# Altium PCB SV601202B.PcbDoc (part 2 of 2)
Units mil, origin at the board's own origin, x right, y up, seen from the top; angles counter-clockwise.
Board outline 3713 x 4037 mil, 6 copper layers (Top Layer, Signal Layer 1, Signal Layer 2, Signal Layer 3, Signal Layer 4, Bottom Layer), stack 60.36 mil thick; 230 components, 115 nets, 621 pads, 197 vias.
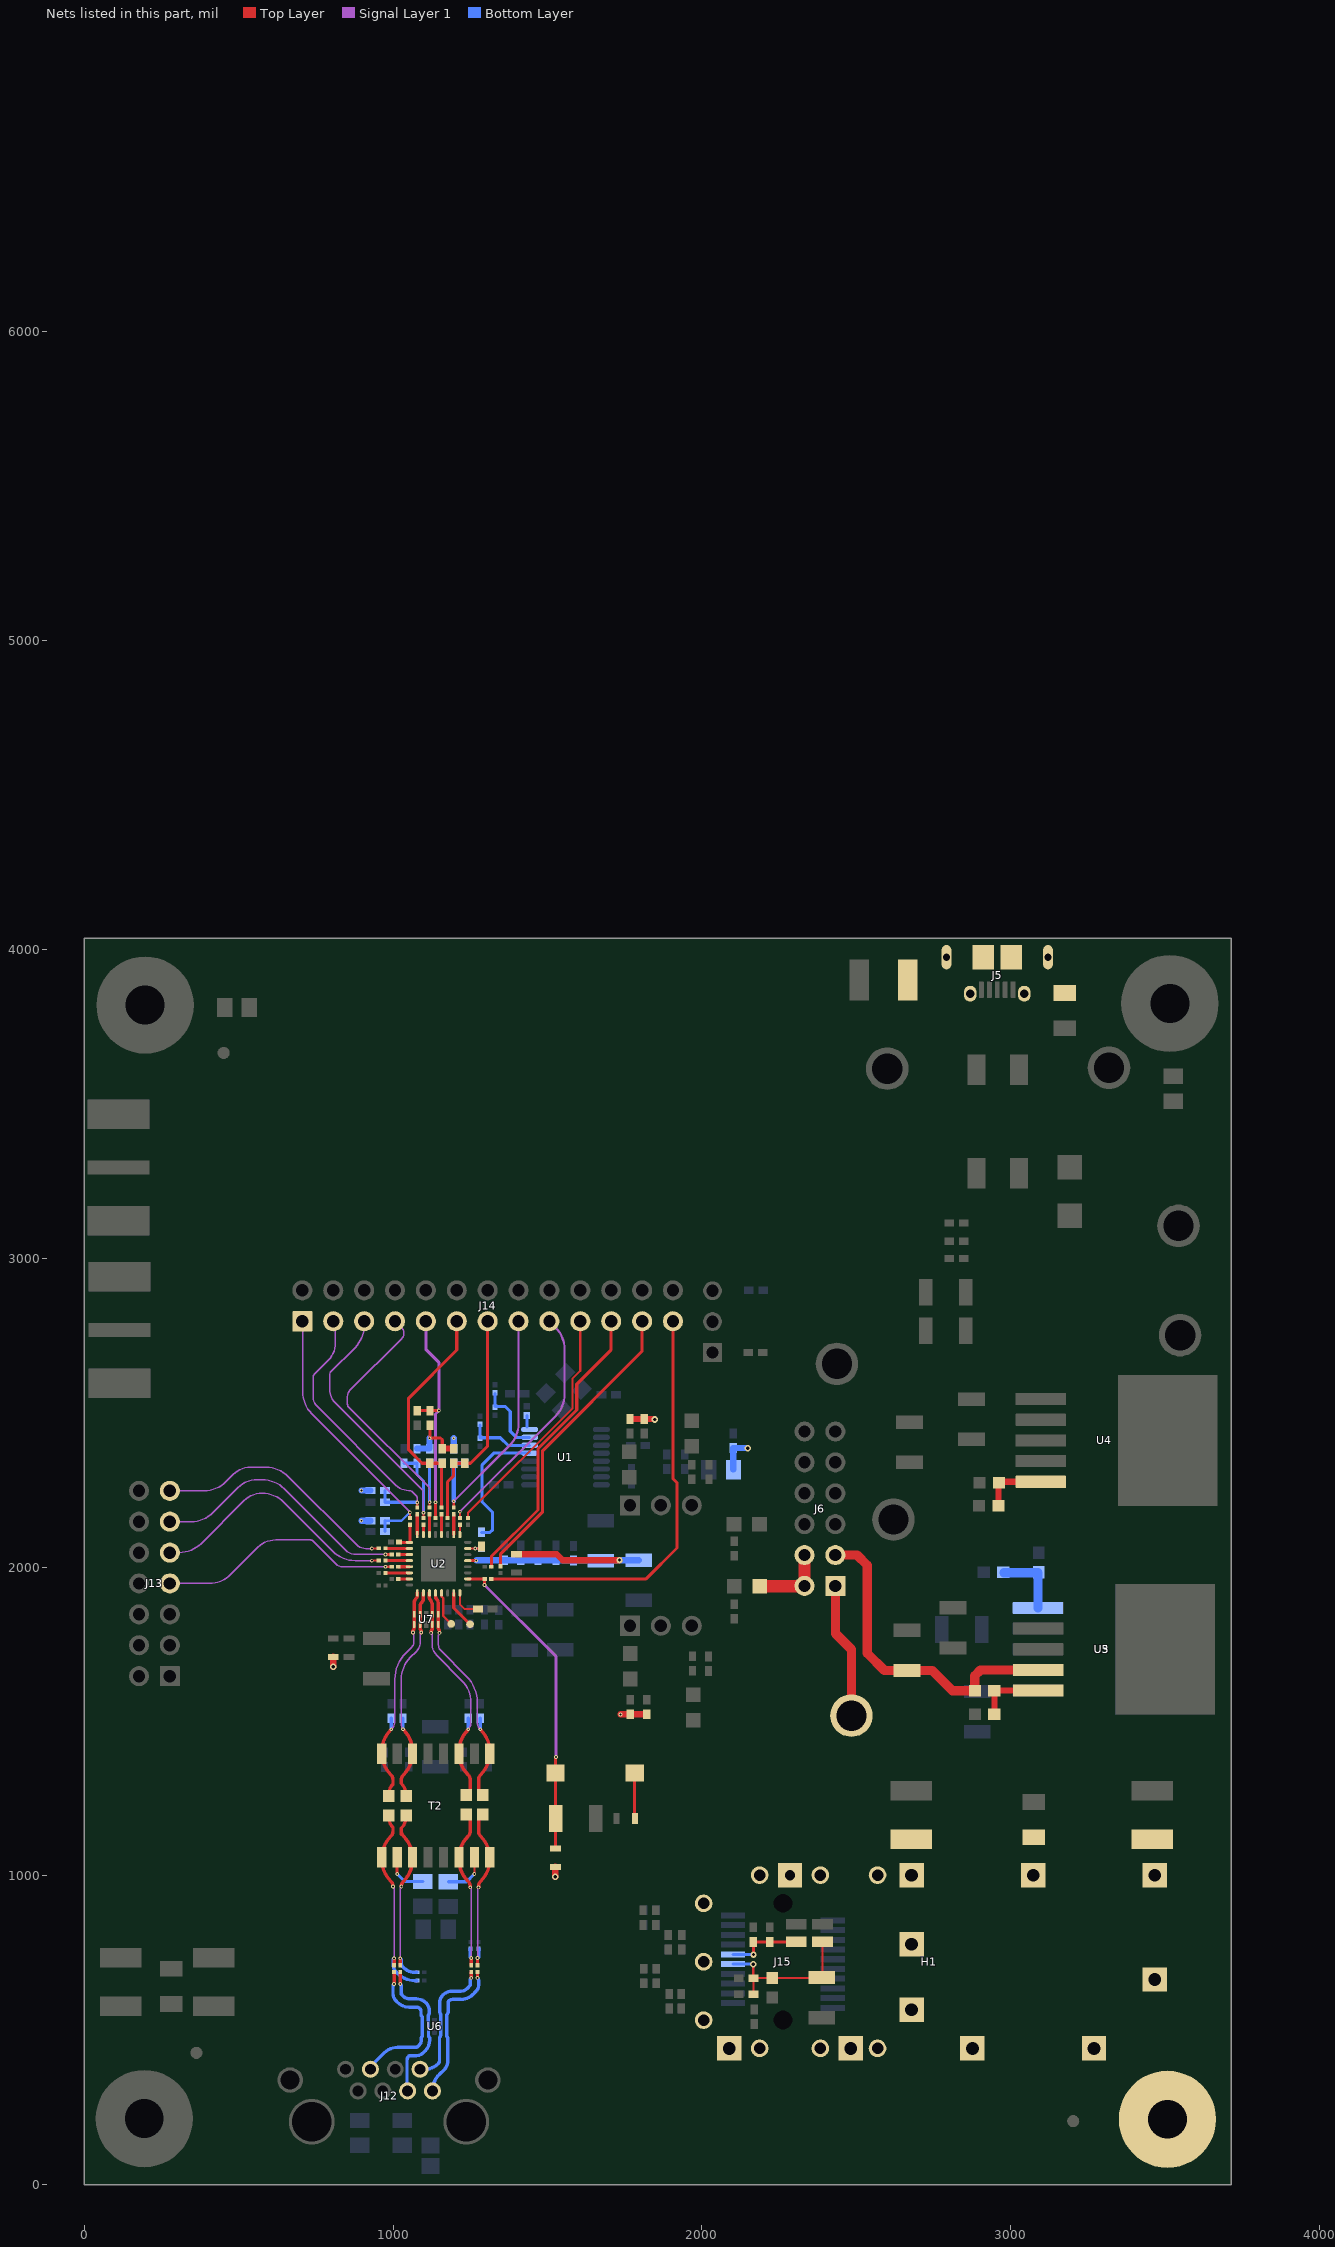
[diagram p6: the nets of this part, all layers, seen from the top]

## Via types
v1: diameter 22, hole 11, Top Layer to Bottom Layer, 107 vias
v2: diameter 12, hole 6, Top Layer to Bottom Layer, 74 vias
v3: diameter 20, hole 10, Top Layer to Bottom Layer, 10 vias
v4: diameter 19.68, hole 7.87, Top Layer to Bottom Layer, 5 vias
v5: diameter 25, hole 12, Top Layer to Bottom Layer, 1 vias

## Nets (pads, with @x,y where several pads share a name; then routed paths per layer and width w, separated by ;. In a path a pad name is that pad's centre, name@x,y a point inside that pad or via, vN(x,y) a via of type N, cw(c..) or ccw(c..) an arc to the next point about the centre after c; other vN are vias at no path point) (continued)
NetJ13_7: J13.7 R50.1 | length 802.7
  Top Layer w7: v2(975,2001) R50.1@994.98,2001
  Signal Layer 1 w4.5: J13.7@277,1947 403.58,1947 ccw(c403.58,2047) 474.29,1976.29 562,2064 cw(c619.94,2006.06) 619.94,2088 730,2088 cw(c730,2071.1) 741.94,2083.06 816,2009 ccw(c835.31,2028.31) 835.31,2001 v2(975,2001)
NetJ13_9: J13.9 R51.1 | length 798.7
  Top Layer w7: v2(931,2021) R51.1@952.98,2021
  Signal Layer 1 w4.5: J13.9@307.58,2047 ccw(c307.58,2147) 378.29,2076.29 516.55,2214.55 cw(c575.58,2155.52) 575.58,2239 cw(c575.58,2139) 646.29,2209.71 805.71,2050.29 ccw(c876.42,2121) 876.42,2021 v2(931,2021)
NetJ13_11: J13.11 R52.1 | length 860.1
  Top Layer w10: v2(975,2041) R52.1@994.98,2041
  Signal Layer 1 w4.5: J13.11@277,2147 345.58,2147 ccw(c345.58,2247) 416.29,2176.29 497,2257 cw(c559.77,2194.23) 559.77,2283 576.58,2283 cw(c576.58,2183) 647.29,2253.71 846,2055 ccw(c879.8,2088.8) 879.8,2041 v2(975,2041)
NetJ13_13: J13.13 R54.1 | length 802.5
  Top Layer w7: v2(931,2060) R54.1@952.98,2060
  Signal Layer 1 w4.5: J13.13@277,2247 387.58,2247 ccw(c387.58,2347) 458.29,2276.29 482,2300 cw(c537.53,2244.47) 537.53,2323 588.58,2323 cw(c588.58,2223) 659.29,2293.71 879.69,2073.31 ccw(c911.83,2105.46) 911.83,2060 v2(931,2060)
NetJ14_1: J14.1 R56.1 R80.1 R82.2 | length 902.6
  Top Layer w7: R56.1@1055,2159.02 v2@1055,2176
  Signal Layer 1 w4.5: J14.1@706,2767 cw(c703.59,2764.59) J14.1@707,2764.59 ; J14.1@707,2796 J14.1@707,2764.59 ; v2@1054,2179 736.29,2496.71 cw(c807,2567.42) 707,2567.42 J14.1@707,2764.59
  Bottom Layer w7: R80.1@973.62,2150 1027,2150 v2(1054,2177)
  Bottom Layer w10: R82.2@973.62,2115 R80.1@973.62,2150
NetJ14_3: J14.3 R57.1 R77.1 R78.2 | length 924
  Top Layer w7: R57.1@1078,2193.02 v2(1078,2209)
  Signal Layer 1 w4.5: J14.3@806,2796 cw(c789.1,2779.1) 813,2779.1 813,2726 cw(c733.33,2726) 789.67,2669.67 746,2626 ccw(c758.07,2613.93) 741,2613.93 741,2551 ccw(c784.46,2551) 753.73,2520.27 1008.32,2265.68 ccw(c1051,2308.36) 1051,2248 cw(c1051,2233.51) 1061.24,2243.76 1074.46,2230.54 cw(c1065.93,2222) 1078,2222 v2(1078,2209)
  Bottom Layer w10: R77.1@973.62,2248 R78.2@973.62,2210 v2@1077,2210
NetJ14_5: J14.5 R58.1 R75.1 R76.2 | length 1012
  Top Layer w7: R58.1@1098,2159.02 v2(1098,2176)
  Signal Layer 1 w4.5: J14.5@906,2796 906,2781.42 cw(c806,2781.42) 876.71,2710.71 798,2632 ccw(c807.66,2622.34) 794,2622.34 794,2578 ccw(c861.6,2578) 813.8,2530.2 1094,2250 cw(c1084.34,2240.34) 1098,2240.34 v2(1098,2176)
  Bottom Layer w10: R76.2@1035,2336.38 R75.1@1077,2336.38 1077,2300 1098,2279 v2(1098,2176)
NetJ14_7: J14.7 R59.1 R71.1 R72.2 | length 963.8
  Top Layer w7: R59.1@1118,2193.02 v2(1118,2210)
  Signal Layer 1 w4.5: J14.7@1006,2796 1028.64,2773.36 cw(c1013.27,2758) 1035,2758 cw(c1008.44,2758) 1027.22,2739.22 860,2572 ccw(c879.31,2552.69) 852,2552.69 852,2528 ccw(c866.49,2528) 856.23,2517.77 1113,2261 cw(c1100.93,2248.93) 1118,2248.93 v2(1118,2210)
  Bottom Layer w10: v2(1118,2210) R71.1@1118,2336.38 R72.2@1159,2336.38
NetJ14_9: J14.9 R61.1 R84.1 R88.2 | length 728.6
  Top Layer w10: R88.2@1078,2506.62 v2@1147.62,2506.62 ; R61.1@1137,2159.02 v2(1137,2210)
  Signal Layer 1 w10: J14.9@1106,2796 1106,2705 1148,2663 v2(1148,2507) 1137,2496 v2(1137,2210)
NetJ14_11: J14.11 R60.1 R62.1 R66.2 | length 746.3
  Top Layer w10: R62.1@1156,2193.02 1156,2333.38 1153,2336.38 R66.2@1118,2336.38 1093.62,2336.38 1050,2380 1050,2547 1206,2703 J14.11@1206,2796
NetJ14_13: J14.13 R53.1 R55.2 R63.1 | length 722.7
  Top Layer w10: R63.1@1176,2159.02 1176,2276 1196,2296 R53.1@1196,2336.38 1250.38,2336.38 1306,2392 J14.13@1306,2796
NetJ14_15: J14.15 R45.1 R48.2 R64.1 | length 845
  Top Layer w7: R64.1@1196,2193.02 v2(1196,2213)
  Signal Layer 1 w7: v2(1196,2213) 1376.71,2393.71 ccw(c1306,2464.42) 1406,2464.42 J14.15@1406,2796
  Bottom Layer w15: v2(1196,2213) R45.1@1196,2336.38 R48.2@1232,2336.38
NetJ14_17: J14.17 R65.1 | length 789.1
  Top Layer w7: R65.1@1216,2159.02 v2(1216,2179)
  Signal Layer 1 w7: v2(1216,2179) 1525.71,2488.71 ccw(c1455,2559.42) 1555,2559.42 1555,2705.58 ccw(c1455,2705.58) 1525.71,2776.29 J14.17@1506,2796
NetJ14_19: J14.19 R67.1 | length 787.8
  Top Layer w7: R67.1@1242,2159.02 1242,2175 1581,2514 1581,2611 1606,2636 J14.19@1606,2796
NetJ14_21: J14.21 R68.1 | length 955.7
  Top Layer w10: R68.1@1318.02,2001 1318.02,2034.02 1469,2185 1469,2382.91 1594.5,2508.41 1594.5,2592.5 1706,2704 J14.21@1706,2796
NetJ14_23: J14.23 R69.1 | length 982.7
  Top Layer w10: R69.1@1348,2003.02 1348,2042.79 1484,2178.79 1484,2376.69 1806,2698.69 J14.23@1806,2796
NetJ14_25: J14.25 R70.1 | length 1381.8
  Top Layer w10: R70.1@1318.02,1962 1819,1962 1919,2062 1919,2273 1906,2286 J14.25@1906,2796
NetR3_1: R3.1 U1.13 | length 433.1
  Bottom Layer w10: R3.1@1286,2112.62 1313.62,2112.62 1322,2121 1322,2177 1288,2211 1288,2331 1325.8,2368.8 U1.13@1441.86,2368.8
NetR10_2: R10.2 S1.2 | length 146.4
  Top Layer w10: R10.2@1781.95,1186.57 S1.2@1781.95,1333
NetR14_1: R14.1 R15.2 U3.5 | length 223.5
  Bottom Layer w30: R14.1@2978.06,1981.44 3087.94,1981.44 U3.5@3087.94,1867.86
NetR19_1: R19.1 R21.2 U4.5 | length 215.6
  Top Layer w7: U4.5@3093.8,2273 U4.5@3096.94,2276.14
  Top Layer w20: R21.2@2960.5,2199 2960.5,2272 R19.1@2961.5,2273 2964.64,2276.14 U4.5@3096.94,2276.14
NetR26_1: R26.1 R27.2 U5.5 | length 219.8
  Top Layer w10: U5.5@3087.8,1600 U5.5@3087.94,1600.14
  Top Layer w20: R27.2@2947.64,1520.86 2947.64,1600.14 U5.5@3087.94,1600.14
NetR34_2: R34.2 T2.10 | length 142.5
  Top Layer w10: v2(1013,1006) T2.10@1013,1055.56
  Bottom Layer w10: v2(1013,1006) 1037,982 R34.2@1096,982
NetR35_2: R35.2 T2.15 | length 143.9
  Top Layer w7: v2(1263,1006) T2.15@1263,1055.56
  Bottom Layer w10: R35.2@1179,981 1238,981 v2(1263,1006)
NetR92_2: R92.2 U1.16 | length 36.6
  Bottom Layer w10: U1.16@1433,2454.43 R92.2@1433,2491.04
NetR93_1: R93.1 R95.2 U1.15 | length 232.8
  Bottom Layer w10: R95.2@1330,2562.04 1330,2519.96 1363.04,2519.96 1379,2504 1379,2440 1399.02,2419.98 U1.15@1441.86,2419.98
NetR94_1: R94.1 R96.2 U1.14 | length 212.1
  Bottom Layer w10: R94.1@1281,2460.04 1281,2418.96 1347.04,2418.96 1371.61,2394.39 U1.14@1441.86,2394.39
NetTP1_1: TP1.1 U2.13 | length 113.4
  Top Layer w7.5: U2.13@1156.84,1916.51 1156.84,1905.16 1162,1900 1162,1842 TP1.1@1188,1816
NetTP2_1: TP2.1 U2.15 | length 123.4
  Top Layer w10: U2.15@1196.21,1916.51 1196.21,1867.79 TP2.1@1249,1815
PWR_CHASSIS: C28.2 J5.6 J5.7 J5.8 J5.9 J5.10 J5.11 R11.1
RBIAS: Rs1.2 U2.16 | length 101.6
  Top Layer w7: U2.16@1215.9,1916.51 1215.9,1880.1 1232,1864 Rs1.2@1274.38,1864
RESET_N: C27.1 R8.1 R70.2 S1.1 U2.18 | length 1021.4
  Top Layer w10: U2.18@1241.49,1961.79 R70.2@1295.76,1961.79 ; v2(1296,1942) R70.2@1295.98,1962 ; R8.1@1526.04,1089.57 C27.1@1526.04,1186 S1.1@1526.05,1333 v2@1526.05,1384.05
  Signal Layer 1 w10: v2(1296,1942) 1527,1711 v2(1527,1385)
RX_CLK: R65.2 U2.25 | length 31.4
  Top Layer w7: U2.25@1215.9,2105.49 R65.2@1215.9,2136.87
RX_D0: R59.2 U2.30 | length 65.6
  Top Layer w10: U2.30@1117.47,2105.49 1117.47,2169.7 cw(c1119.27,2169.7) R59.2@1118,2170.98
RX_D1: R58.2 U2.31 | length 31.3
  Top Layer w10: U2.31@1097.79,2105.49 R58.2@1097.79,2136.76
RX_D2: R57.2 U2.32 | length 65.4
  Top Layer w10: U2.32@1078.1,2105.49 R57.2@1078.1,2170.87
RX_D3: R7.2 R56.2 U2.1 | length 89.9
  Top Layer w10: R7.2@1020.09,2079.9 U2.1@1052.51,2079.9 ccw(c1048.92,2083.49) 1054,2083.49 R56.2@1054,2136.98
RX_DV: R64.2 U2.26 | length 65.3
  Top Layer w10: U2.26@1196.21,2105.49 R64.2@1196.21,2170.76
RX_ER: R62.2 U2.28 | length 65.7
  Top Layer w10: R62.2@1156,2170.98 cw(c1153.97,2168.94) 1156.84,2168.94 U2.28@1156.84,2105.49
RXD_CABLE_N: J12.6 R28.2 U6.5 U6.6 | length 496.4
  Top Layer w11: v2(1003,650) R28.2@1003,688.98
  Bottom Layer w11: J12.6@926.37,373.99 cw(c946.6,373.99) 932.29,388.29 971,427 cw(c1014.46,383.54) 1014.46,445 1074.17,445 ccw(c1074.17,451.83) 1078.99,446.99 1085.3,453.3 ccw(c1071.59,467) 1090.97,467 1090.97,476.28 ccw(c1082.14,485.11) 1094.63,485.11 1094.63,496.27 1094.63,529.73 1094.63,539.24 ccw(c1082.24,539.24) 1091,548 cw(c1093.41,550.41) 1090,550.41 1090,562.76 ccw(c1079.76,562.76) 1087,570 ccw(c1074.93,557.93) 1074.93,575 1052.31,575 cw(c1052.31,629.31) 1013.91,590.91 1009.18,595.64 cw(c1032.54,619) 999.5,619 999.5,641.55 cw(c1011.45,641.55) v2(1003,650)
RXD_CABLE_P: J12.3 R29.2 U6.4 U6.7 | length 498.9
  Top Layer w11: v2(1023,650) R29.2@1023,688.98
  Bottom Layer w11: v2(1023,650) cw(c1014.55,641.55) 1026.5,641.55 1026.5,619 ccw(c1032.54,619) 1028.27,614.73 1033,610 ccw(c1052.31,629.31) 1052.31,602 1074.93,602 cw(c1074.93,557.93) 1106.09,589.09 cw(c1079.76,562.76) 1117,562.76 1117,557 cw(c1104.93,557) 1113.46,548.46 1113.46,531.79 ccw(c1116.37,531.79) 1114.32,529.73 1114.32,496.27 1114.32,485.11 ccw(c1126.8,485.11) 1117.97,476.28 1117.97,467 cw(c1071.59,467) 1104.39,434.2 1098.09,427.91 cw(c1074.17,451.83) 1074.17,418 1054,418 ccw(c1054,413.17) 1050.59,416.59 ccw(c1064.69,402.48) 1044.74,402.48 1044.74,308.98 ccw(c1051.91,308.98) J12.3@1046.84,303.91
RXD_MAG_N: C47.1 R28.1 R36.1 T2.9 | length 630.6
  Top Layer w11: C47.1@986,1195.5 986,1189.41 ccw(c1032.09,1189.41) 999.5,1156.82 999.5,1145.36 cw(c974.88,1145.36) 992.29,1127.95 ccw(c1063,1057.24) 963,1057.24 963,1055.56 963,1053.88 ccw(c1063,1053.88) 992.29,983.17 cw(c974.88,965.76) v2(999.5,965.76) ; R28.1@1003,711.02 v2(1003,733)
  Signal Layer 1 w4.5: v2(999.5,965.76) cw(c991.65,957.92) 1002.75,957.92 v2@1002.75,733
  Bottom Layer w11: v2(1003,733) ccw(c1011.45,724.55) 999.5,724.55 999.5,714 ccw(c1034.95,714) 1009.88,688.93 1014.91,683.91 ccw(c1070.21,739.21) 1070.21,661 R36.1@1076,661
RXD_MAG_P: C48.1 R29.1 R41.1 T2.11 | length 599.9
  Top Layer w11: R29.1@1023,711.02 v2(1023,733) ; v2(1026.5,965.76) cw(c1051.12,965.76) 1033.71,983.17 ccw(c963,1053.88) 1063,1053.88 1063,1055.56 1063,1057.24 ccw(c963,1057.24) 1033.71,1127.95 cw(c1051.12,1145.36) 1026.5,1145.36 ; 1026.5,1134.17 1026.5,1145.36 ; C48.1@1042,1195.5 1042,1192.24 cw(c989.08,1192.24) 1026.5,1154.82 1026.5,1145.36
  Signal Layer 1 w4.5: v2@1023.25,733 1023.25,957.92 cw(c1034.35,957.92) v2(1026.5,965.76)
  Bottom Layer w11: v2(1023,733) cw(c1014.55,724.55) 1026.5,724.55 1026.5,714 ccw(c1034.95,714) 1028.97,708.03 1034,703 ccw(c1070.21,739.21) 1070.21,688 R41.1@1076,688
RXD_N: C47.2 R39.1 T2.8 U2.9 U7.1 U7.10 | length 739.4
  Top Layer w11: C47.2@986,1258.5 986,1264.59 cw(c1032.09,1264.59) 999.5,1297.18 999.5,1310.65 ccw(c974.88,1310.65) 992.29,1328.05 cw(c1063,1398.76) 963,1398.76 963,1400.44 963,1402.12 cw(c1063,1402.12) v2@992.29,1472.83 ; v2(1063.97,1788) 1063.97,1794.28 ccw(c1055.14,1803.11) 1067.63,1803.11 1067.63,1814.27 1067.63,1847.73 1067.63,1881.21 cw(c1092.79,1881.21) 1075,1899 ccw(c1067.51,1906.49) 1078.1,1906.49 U2.9@1078.1,1916.51
  Signal Layer 1 w4.5: v2(994,1475) ccw(c966.24,1502.76) 1005.5,1502.76 1005.5,1636.59 cw(c1126,1636.59) 1040.79,1721.79 1059.6,1740.6 ccw(c1041.2,1759) 1067.22,1759 1067.22,1780.15 ccw(c1056.13,1780.15) v2(1063.97,1788)
  Bottom Layer w11: v2(994,1475) R39.1@994,1510.38
RXD_P: C48.2 R40.1 T2.6 U2.10 U7.2 U7.9 | length 738.5
  Top Layer w11: v2@1033.71,1472.83 cw(c963,1402.12) 1063,1402.12 1063,1400.44 1063,1398.76 cw(c963,1398.76) 1033.71,1328.05 ccw(c1051.12,1310.65) 1026.5,1310.65 1026.5,1299.18 cw(c989.08,1261.76) 1042,1261.76 C48.2@1042,1258.5 ; v2(1090.97,1788) 1090.97,1794.28 cw(c1099.8,1803.11) 1087.31,1803.11 1087.31,1814.27 1087.31,1847.73 1087.31,1873.69 cw(c1103.31,1873.69) 1092,1885 ccw(c1078.03,1898.97) 1097.79,1898.97 U2.10@1097.79,1916.51
  Signal Layer 1 w4.5: v2(1032,1475) cw(c1046.49,1489.49) 1026,1489.49 1026,1636.59 cw(c1126,1636.59) 1055.29,1707.3 1074.1,1726.11 ccw(c1041.2,1759) 1087.72,1759 1087.72,1780.15 cw(c1098.82,1780.15) v2(1090.97,1788)
  Bottom Layer w11: v2(1032,1475) R40.1@1032,1510.38
SFP_EARTH: C66.2 C67.2 H1.1 H1.2 H1.3 H1.4 H1.5 H1.6 H1.7 H1.8 H1.9 H1.10 H1.11 H1.12 H1.MH1 H1.MH2 H1.MH3 H1.MH4 H1.MH5 H1.MH6 H1.MH7 H1.MH8 M2.1 R83.1
TX_CLK: R54.2 U2.2 | length 77.3
  Top Layer w10: R54.2@975.24,2060.21 U2.2@1052.51,2060.21
TX_D0: R51.2 U2.4 | length 77.3
  Top Layer w10: R51.2@975.18,2020.84 U2.4@1052.51,2020.84
TX_D1: R50.2 U2.5 | length 35.3
  Top Layer w10: R50.2@1017.18,2001.16 U2.5@1052.51,2001.16
TX_D2: R49.2 U2.6 | length 77.6
  Top Layer w10: R49.2@975.02,1982 ccw(c976.3,1983.27) 976.3,1981.47 U2.6@1052.51,1981.47
TX_D3: R47.2 U2.7 | length 35.3
  Top Layer w10: R47.2@1017.24,1961.79 U2.7@1052.51,1961.79
TX_EN: R52.2 U2.3 | length 35.6
  Top Layer w10: R52.2@1017.02,2041 ccw(c1018.16,2042.14) 1018.16,2040.53 U2.3@1052.51,2040.53
TXD_CABLE_N: J12.2 R30.2 U6.2 U6.9 | length 434.1
  Top Layer w11: v2(1253,670) R30.2@1253,688.98
  Bottom Layer w11: J12.2@1087,373.99 1102.53,373.99 ccw(c1102.53,435.47) 1146,392 ccw(c1136.28,401.72) 1150.03,401.72 1150.03,476.28 ccw(c1141.2,485.11) 1153.69,485.11 1153.69,496.27 U6.9@1153.69,529.73 ; U6.9@1153.91,529.96 1153.91,552.91 cw(c1160.93,559.93) 1151,559.93 1151,590.17 cw(c1184.83,590.17) 1160.91,614.09 cw(c1192.07,582.93) 1192.07,627 1219.69,627 ccw(c1219.69,654.31) 1238.99,634.99 1249.5,645.5 1249.5,661.55 cw(c1261.45,661.55) v2(1253,670)
TXD_CABLE_P: J12.1 R31.2 U6.1 U6.10 | length 473.6
  Top Layer w11: v2(1273,670) R31.2@1273,688.98
  Bottom Layer w11: J12.1@1127.16,303.91 cw(c1202.14,303.91) 1149.11,356.93 1165.09,372.91 ccw(c1136.28,401.72) 1177.03,401.72 1177.03,476.28 cw(c1185.86,485.11) 1173.37,485.11 1173.37,496.27 1173.37,529.73 1173.37,547.65 cw(c1182.35,547.65) 1176,554 ccw(c1171.17,558.83) 1178,558.83 1178,590.17 cw(c1184.83,590.17) 1180,595 cw(c1192.07,582.93) 1192.07,600 1219.69,600 ccw(c1219.69,654.31) 1258.09,615.91 1268.24,626.05 ccw(c1248.29,646) 1276.5,646 1276.5,661.55 ccw(c1264.55,661.55) v2(1273,670)
TXD_MAG_N: C49.1 R30.1 R42.1 T2.14 | length 543.6
  Top Layer w11: C49.1@1237,1198.5 1242.5,1193 cw(c1224.39,1174.9) 1250,1174.9 1250,1148 ; v2(1249.5,963) 1249.5,965.76 ccw(c1224.88,965.76) 1242.29,983.17 cw(c1313,1053.88) 1213,1053.88 1213,1055.56 1213,1057.24 cw(c1313,1057.24) 1242.29,1127.95 ccw(c1224.88,1145.36) 1249.5,1145.36 1249.5,1148 ; v2(1252.75,734) 1253,733.75 R30.1@1253,711.02
  Signal Layer 1 w4.5: v2(1249.5,963) cw(c1241.65,955.15) 1252.75,955.15 v2(1252.75,734)
  Bottom Layer w11: R42.1@1249.5,764 1249.5,737.25 v2(1252.75,734)
TXD_MAG_P: C50.1 R31.1 R44.1 T2.16 | length 543.6
  Top Layer w11: R31.1@1273,711.02 1273,733.75 v2(1273.25,734) ; v2(1276.5,963) 1276.5,965.76 cw(c1301.12,965.76) 1283.71,983.17 ccw(c1213,1053.88) 1313,1053.88 1313,1055.56 1313,1057.24 ccw(c1213,1057.24) 1283.71,1127.95 cw(c1301.12,1145.36) 1276.5,1145.36 1276.5,1148 ; 1277,1148 1277,1174.9 cw(c1302.61,1174.9) 1284.5,1193 C50.1@1290,1198.5
  Signal Layer 1 w4.5: v2(1273.25,734) 1273.25,955.15 cw(c1284.35,955.15) v2(1276.5,963)
  Bottom Layer w11: v2(1273.25,734) 1276.5,737.25 R44.1@1276.5,764
TXD_N: C49.2 R37.1 T2.3 U2.11 U7.4 U7.7 | length 762.5
  Top Layer w11: U2.11@1117.47,1916.51 1117.47,1900.1 ccw(c1126.1,1900.1) 1120,1894 cw(c1103.86,1877.86) 1126.69,1877.86 1126.68,1847.73 1126.68,1814.27 1126.68,1803.11 cw(c1114.2,1803.11) 1123.03,1794.28 v2(1123.03,1787) ; C49.2@1237,1261.5 1242.5,1267 ccw(c1224.39,1285.1) 1250,1285.1 1250,1310 ; v2@1242.29,1472.83 ccw(c1313,1402.12) 1213,1402.12 1213,1400.44 1213,1398.76 ccw(c1313,1398.76) 1242.29,1328.05 cw(c1224.88,1310.65) 1249.5,1310.65 1249.5,1310
  Signal Layer 1 w4.5: v2(1123.03,1787) cw(c1115.18,1779.15) 1126.28,1779.15 1126.28,1748.85 ccw(c1174.85,1748.85) 1140.5,1714.5 1222.71,1632.3 cw(c1152,1561.59) 1252,1561.59 1252,1496.73 cw(c1221.27,1496.73) v2(1243,1475)
  Bottom Layer w11: v2(1243,1475) R37.1@1243,1510.38
TXD_P: C50.2 R38.1 T2.1 U2.12 U7.5 U7.6 | length 761
  Top Layer w11: U2.12@1137.16,1916.51 1137.16,1903.86 ccw(c1146.86,1903.86) 1140,1897 cw(c1124.62,1881.62) 1146.37,1881.62 1146.37,1847.73 1146.37,1814.27 1146.37,1803.11 ccw(c1158.86,1803.11) 1150.03,1794.28 v2(1150.03,1787) ; 1276.5,1310 1276.5,1310.65 cw(c1301.12,1310.65) 1283.71,1328.05 ccw(c1213,1398.76) 1313,1398.76 T2.1@1313,1400.44 ; 1277,1310 1277,1285.1 ccw(c1302.61,1285.1) 1284.5,1267 C50.2@1290,1261.5 ; v2@1283.71,1472.83 cw(c1213,1402.12) T2.1@1313,1402.12
  Signal Layer 1 w4.5: v2(1150.03,1787) ccw(c1157.87,1779.15) 1146.78,1779.15 1146.78,1748.85 ccw(c1174.85,1748.85) 1155,1729 1237.21,1646.79 cw(c1152,1561.59) 1272.5,1561.59 1272.5,1497.93 ccw(c1304.93,1497.93) v2(1282,1475)
  Bottom Layer w11: v2(1282,1475) R38.1@1282,1510.38
VCC_R: C57.1 C58.1 C59.1 J15.15 L4.2 R73.2 | length 488.2
  Top Layer w7: v3(2166,714) C57.1@2166,669.62 ; C58.1@2166.62,617 C57.1@2166.62,669 C57.1@2166.01,669.62 ; C59.1@2375,673.03 cw(c2370,673.03) 2373.54,669.5 R73.2@2227,669.5 2226.5,669 2167.5,669 cw(c2167.5,671.12) C57.1@2166.01,669.62 ; C59.1@2390,672.96 L4.2@2390,786.46
  Bottom Layer w7: v3@2165.6,714.4 v3(2166,714)
  Bottom Layer w10: J15.15@2100.58,714.4 v3@2165.6,714.4
VCC_T: C53.1 C54.1 J15.16 L3.2 | length 248.2
  Top Layer w10: v3(2167,745) 2167,783.96 ccw(c2163.59,783.96) C54.1@2166,786.38 C53.1@2219,786.38 L3.2@2307,786.38
  Bottom Layer w10: J15.16@2100.58,745.9 v3@2166.1,745.9
VDDIO: C6.1 C12.1 C13.1 C14.1 C15.1 C16.1 C17.1 C18.1 D2.1 J6.2 J6.4 L2.1 R5.2 R6.2 R8.2 R16.1 R17.2 R22.1 R23.2 R45.2 R53.2 R60.2 R71.2 R75.2 R77.2 R80.2 R84.2 U2.21 | length 1798.7
  Top Layer w10: R84.2@1119,2459.38 1119,2418 1153,2418 1159,2412 R60.2@1159,2383.62 ; U2.21@1241.49,2020.84 v2@1268.84,2020.84
  Top Layer w20: v1(806,1677) R6.2@806,1709.47 ; R60.2@1159,2383.62 R53.2@1196,2383.62 ; R5.2@1400,2041.53 1529.47,2041.53 1548.66,2022.34 v3(1733,2022.34) ; v1(1525,997) R8.2@1525,1029.47 ; v2@1736.38,1523.38 R17.2@1768,1523.38 R16.1@1821,1523.38 ; R23.2@1767,2479.62 R22.1@1813,2479.62 v1@1845.38,2479.62
  Top Layer w40: D2.1@2186.65,1938.15 2331.15,1938.15 J6.2@2332,1939 J6.4@2332,2039
  Bottom Layer w20: v2(897,2150) R80.2@926.38,2150 ; v2(897,2248) R77.2@926.38,2248 ; R75.2@1077,2383.62 R71.2@1118,2383.62 v2(1118,2417) ; R45.2@1196,2383.62 v2(1196,2417) ; v2@1269.96,2021.96 C12.1@1795,2021.96 ; L2.1@2101,2316 C6.1@2101,2385.38 v1@2147.62,2385.38
  other v1: 2148,2385 1847,2478
  other v2: 1736,1523 1269,2021
VDDIO_EXT: J6.1 J7.1 | length 441.5
  Top Layer w30: J6.1@2432,1939 2432,1785 2484,1733 J7.1@2484,1519
VDDIO_INT: C39.1 J6.3 R26.2 U5.4 | length 1061.9
  Top Layer w30: J6.3@2432,2039 2502,2039 2535,2006 2535,1721 2590.96,1665.04 2745.96,1665.04 2811,1600 R26.2@2883.5,1600 2883.5,1648.5 2902.07,1667.07 U5.4@3088.94,1667.07
XI: R3.2 R4.2 U2.23 | length 61.3
  Top Layer w7: U2.23@1241.49,2060.21 1280.83,2060.21 R4.2@1286,2065.38
  Bottom Layer w7: v2(1266,2060) R3.2@1280.62,2060
pads on no net: FID1.1 FID2.1 FID3.1 J5.2 J5.3 J5.4 J15.2 J15.4 J15.5 J15.6 J15.7 J15.MH1 J15.MH2 LBL1.0 SH-J2.0 SH-J6A.0 SH-J6B.0 SH-J6C.0 SH-J10.0 T2.4 T2.5 T2.12 T2.13 U1.4 U1.7 U1.8 U1.10 U1.11 U2.22 U6.3@1134,496.56 U6.8@1134,529.44 U7.3@1107,1814.56 U7.8@1107,1847.44

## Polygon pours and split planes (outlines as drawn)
EARTH on Signal Layer 2 "Signal Layer 2-EARTH" (solid, remove dead copper, pour order 26): 1,620 579,620 579,509 706,382 816,272 1175,272 1300,397 1375,397 1375,132 1376,1 1376.08,0.11 1375,0 1374.99,1 1,1 0,0
VDDIO on Signal Layer 2 "Signal Layer 2-VDDIO" (solid, remove dead copper, pour order 27): 0,0 3713,0 3713,4037 0,4037
5V_20V on Top Layer "Top Layer-5V_20V" (solid, remove dead copper, pour order 18): 3613,3178 2830,3178 2830,2457 2831,2456 2832,2455 3180,2455 3180,3032 3613,3032
SFP_EARTH on Top Layer "Top Layer-SFP_EARTH" (solid, remove dead copper, pour order 22): 1962,1150 1962,400 3704,400 3704,1151
PWR_CHASSIS on Top Layer "Top Layer-PWR_CHASSIS" (solid, remove dead copper, pour order 21): 2634,4031 2634,3831 2893,3831 2893,3937 3023,3937 3023,3832 3138,3832 3241,3832 3241,4031
EARTH on Top Layer "Top Layer-Earth" (solid, remove dead copper, pour order 19): 1,620 579,620 579,509 706,382 816,272 1175,272 1300,397 1375,397 1375,132 1376,1 1376.08,0.11 1375,0 1374.99,1 1,1 0,0
SFP_EARTH on Top Layer "Top Layer-SFP_EARTH1" (solid, remove dead copper, pour order 23): 1962,1150 1962,400 3341,400 3341,0 3713,0 3704,400 3704,1151
GND on Top Layer "Top Layer-GND" (solid, remove dead copper, pour order 24): 0,0 3713,0 3713,4037 0,4037
EARTH on Signal Layer 1 "Signal Layer 1-EARTH" (solid, remove dead copper, pour order 25): 1,620 579,620 579,509 706,382 816,272 1175,272 1300,397 1375,397 1375,132 1376,1 1376.08,0.11 1375,0 1374.99,1 1,1 0,0
GND on Bottom Layer "Bottom Layer-GND" (solid, remove dead copper, pour order 34): 0,0 3713,0 3713,4043 0,4043
EARTH on Bottom Layer "Bottom Layer-Earth" (solid, remove dead copper, pour order 33): 1,620 579,620 579,509 706,382 816,272 1175,272 1300,397 1375,397 1375,1 1,1 0,0
3V3 on Signal Layer 4 "Signal Layer 2-3V3" (solid, remove dead copper, pour order 30): 2284,2290 2190,2290 2190,1607 2190,1487 1554,1487 1554,1607 915,1607 919,1603 919,1322 1774,1322 1774,512 1952,512 1953,511 1956,514 1956,1322 2284,1322 2284,2090 2383,2090 2383,2285 2383,2290 2327,2290
EARTH on Signal Layer 4 "Signal Layer 4-Earth" (solid, remove dead copper, pour order 31): 1,620 579,620 579,509 706,382 816,272 1175,272 1300,397 1375,397 1375,1 1,1 0,0
GND on Signal Layer 4 "Signal Layer 4-GND" (solid, remove dead copper, pour order 32): 0,0 3713,0 3713,4033 0,4033
GND on Signal Layer 3 "Signal Layer 3-GND" (solid, remove dead copper, pour order 29): 0,0 3713,0 3713,4029 0,4029
EARTH on Signal Layer 3 "Signal Layer 3-Earth" (solid, remove dead copper, pour order 28): 1,620 579,620 579,509 675.86,412.14 678.41,411.02 681.33,411.02 681.33,395.44 920.19,395.44 945,397 945,1015 981.02,1015 1085,1015 1286,1015 1330,1015 1330,397 1375,397 1375,1 1,1 0,0

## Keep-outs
Keep-Out Layer:
  lines w5: -1,2 1,0 ; 3709,0 3712,3 ; 3712,4037 3713,4038
  lines w10: -1,2 -1,4038 3713,4038 ; 1,0 3709,0 ; 3712,3 3712,4037 ; -5,-204 ccw(c0,-204) 0,-209 cw(c0,-204) -5,-204

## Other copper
Top Layer:
  pour cut-out: 1944.81,784.13 1945,784.32 1945,1169 3713,1169 3713,1152 1961,1152 1963,1150 1963,400 3340,400 3340,1 3322,1 3322,379 1945,379 1945,783
  pour cut-out: 882,674 882,1483 946,1483 1329,1483 1394,1483 1394,460 1698,460 1698,0 1641,0 1641,396 1640,397 1300,397 1175,272 816,272 579,509 579,620 0,620 0,674
  pour cut-out: 2540,3775 3226,3775 3290,3775 3290,4037 3242,4037 3242,3832 3139,3832 2634,3832 2634,4037 2540,4037
  pour cut-out: 1737.38,1689.72 1737.38,1668.28 1795.83,1668.28 1798.62,1671.08 1798.62,1689.72
  pour cut-out: 2266.54,819.81 2266.54,810.19 2430.46,810.19 2430.46,819.81
  pour cut-out: 2201.3,642.81 2201.3,633.19 2252.7,633.19 2252.7,642.81
  pour cut-out: 2337.69,642.31 2337.69,569.69 2438.31,569.69 2438.31,642.31
  pour cut-out: 1734.38,2342.72 1734.38,2321.28 1795.62,2321.28 1795.62,2342.72
  pour cut-out: 2925.19,2298.7 2934.81,2298.7 2934.81,2247.3 2925.19,2247.3
  pour cut-out: 2134.59,1968.77 2156.02,1968.77 2156.02,1907.53 2134.59,1907.53
  pour cut-out: 2134.28,2169.62 2155.72,2169.62 2155.72,2108.38 2134.28,2108.38
Signal Layer 1:
  pour cut-out: 882,674 882,1483 946,1483 1329,1483 1394,1483 1394,460 1698,460 1698,0 1641,0 1641,396 1640,397 1300,397 1175,272 816,272 579,509 579,620 0,620 0,674
Signal Layer 2:
  pour cut-out: 882,674 882,1483 946,1483 1329,1483 1394,1483 1394,460 1698,460 1698,0 1641,0 1641,396 1640,397 1300,397 1175,272 816,272 579,509 579,620 0,620 0,674
Signal Layer 3:
  pour cut-out: 884,1483 1393,1483 1393,404.14 1646.59,404.14 1646.59,0 1698,0 1698,404.14 1698,460 1393,460 1393,404.14 1337.14,404.14 1328.86,1021 945,1010 945,674 884,674
  pour cut-out: 0,674 938,674 938,402 686.3,402 686.15,401.85 579,509 579,620 0,620
Signal Layer 4:
  pour cut-out: 882,674 882,1483 946,1483 1329,1483 1394,1483 1394,460 1698,460 1698,0 1641,0 1641,396 1640,397 1300,397 1175,272 816,272 579,509 579,620 0,620 0,674
Bottom Layer:
  pour cut-out: 882,674 882,1483 946,1483 1329,1483 1394,1483 1394,460 1698,460 1698,0 1641,0 1641,396 1640,397 1300,397 1175,272 816,272 579,509 579,620 0,620 0,674

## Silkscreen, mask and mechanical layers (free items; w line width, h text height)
Top Overlay:
  region: 2044,3399 1744,3399 1744,3299 2044,3299
  lines w4: 1781,2063 1838,2063 1838,2141 1782,2141 1781,2142 1781,2063 ; 1784,1885 1784,1964 1785,1963 1841,1963 1841,1885 1784,1885 ; 1899,2063 1951,2063 1952,2064 1952,2142 1899,2142 1899,2063 ; 1900,1886 1900,1965 1953,1965 1953,1887 1952,1886 1900,1886
  lines w10: 1701.78,3210.14 1702.28,3210.64 ; 2278,2882 2278,3363 2578,3363 2578,2882 2278,2882
  text "DP83822EVM" at 980,3581 h100
  text "AVD INT" at 2328,3300 h30
  text "SV601202-" at 843,3293 h100
  text "AVD EXT" at 2328,3224 h30
  text "CT EXT" at 2344,3146 h30
  text "CT INT" at 2344,3064 h30
  text "REV B" at 848,3051 h100
  text "VDDIO INT" at 2306,2993 h30
  text "50MHz" at 1972,2971 h30
  text "VDDIO EXT" at 2303,2927 h30
  text "GND" at 539,2882 h30
  text "COL" at 1124,2653 h30 r90
  text "CRS" at 1321,2651 h30 r90
  text "MDC" at 1722,2648 h30 r90
  text "RXD1" at 922,2633 h30 r90
  text "MDIO" at 1825,2625 h30 r90
  text "RXD2" at 821,2623 h30 r90
  text "RXD0" at 1023,2623 h30 r90
  text "RXD3" at 720,2622 h30 r90
  text "25MHz" at 1974,2592 h30
  text "RX_ER" at 1220,2591 h30 r90
  text "RESET" at 1920,2591 h30 r90
  text "RX_DV" at 1426,2590 h30 r90
  text "RX_CLK" at 1524.59,2560.16 h30 r90
  text "LED_GPIO" at 1624,2510 h30 r90
  text "TX_CLK" at 343,2239 h30
  text "AVD_LED" at 2052.39,2189.69 h25
  text "TX_EN" at 343,2140 h30
  text "SPEED" at 1617,2092 h30
  text "PU" at 1824,2074 h30 r90
  text "PD" at 1942,2074 h30 r90
  text "TXD0" at 343,2034 h30
  text "VDDIO_LED" at 2019,1974 h25
  text "TXD1" at 343,1939 h30
  text "LINK/ACT" at 1535,1902 h30
  text "PD" at 1943,1897 h30 r90
  text "PU" at 1827,1896 h30 r90
  text "TXD2" at 345,1839 h30
  text "TXD3" at 346,1738 h30
  text "INT/PWDN_N" at 346,1636 h30
  text "GND" at 189,1492 h30 r90
M1 Board Outline:
  the board outline again, w10
M2 Board Dimensions:
  rectangle: 0,-479 125,-354
  rectangle: 125,-604 500,-479
  lines w7: 0,-479 1000,-479 ; 125,-604 125,-354 ; 250,-604 250,-354 ; 500,-604 500,-354 ; 750,-604 750,-354 ; 0,-604 1000,-604 1000,-354 0,-354 0,-604
M5 Assembly Top:
  lines w10: -292,-1134.17 6308,-1134.17 ; -292,-930.83 6310,-930.83 ; -292,-727.5 -292,-1337.5 3713,-1337.5 6310,-1337.5 6310,-727.5 -291.5,-727.5 -291.5,-1337.5 1284,-1337.5 ; 2173,-1337.5 2173,-727.5 ; 3440,-930.83 3440,-727.5 ; 4280,-930.83 4280,-727.5 ; 4902,-1344 4902,-1141.17
  text "COMPONENTS MARKED 'DNP' SHOULD NOT BE POPULATED." at 1153.5,-522.5 h60
  text "ASSEMBLY VARIANT:" at 1153,-638 h60
  text ".VariantName" at 2189,-638 h60
  text "PCB VIEWED FROM TOP SIDE" at -228.5,-859.67 h60
  text "BOARD #:" at 2248,-859.67 h60
  text ".PRJ_Number" at 2793.5,-859.67 h60
  text "REV:" at 3638,-859.67 h60
  text ".PCB_Rev" at 3929.5,-859.67 h60
  text "SVN REV:" at 4476,-859.67 h60
  text ".VersionControl_RevNumber" at 4982,-859.67 h60
  text "TID #:" at 2248,-1063 h60
  text ".TID" at 2793.5,-1063 h60
  text "PLOT NAME =" at -228.5,-1268.34 h60
  text ".plot_File_Name" at 577,-1268.34 h60
  text "GENERATED    :" at 2250,-1268.34 h60
  text ".Print_Date" at 3119.5,-1268.34 h60
  text ".Print_Time" at 3848.5,-1268.34 h60
  text "TEXAS INSTRUMENTS" at 5113,-1268.34 h60
M6 Assembly Bottom:
  lines w10: -292.5,-931.33 6309.5,-931.33 ; -290.5,-1134.67 6309.5,-1134.67 ; 1115.5,-1344.5 1115.5,-1141.67 ; 1737.5,-931.33 1737.5,-728 ; 2577.5,-931.33 2577.5,-728 ; 3844.5,-1338 3844.5,-728 ; 4733.5,-1338 6309,-1338 6309,-728 -292.5,-728 -292.5,-1338 2304.5,-1338 6309.5,-1338 6309.5,-728
  text "COMPONENTS MARKED 'DNP' SHOULD NOT BE POPULATED." at 6102,-522 h60
  text ".VariantName" at 5058,-638 h60
  text "ASSEMBLY VARIANT:" at 6097,-638 h60
  text ".VersionControl_RevNumber" at 1035.5,-860.17 h60
  text "SVN REV:" at 1541.5,-860.17 h60
  text ".PCB_Rev" at 2088,-860.17 h60
  text "REV:" at 2379.5,-860.17 h60
  text ".PRJ_Number" at 3224,-860.17 h60
  text "BOARD #:" at 3769.5,-860.17 h60
  text "PCB VIEWED FROM BOTTOM SIDE" at 6246,-860.17 h60
  text ".TID" at 3224,-1063.5 h60
  text "TID #:" at 3769.5,-1063.5 h60
  text "TEXAS INSTRUMENTS" at 904.5,-1268.84 h60
  text ".Print_Time" at 2169,-1268.84 h60
  text ".Print_Date" at 2898,-1268.84 h60
  text "GENERATED    :" at 3767.5,-1268.84 h60
  text ".plot_File_Name" at 5440.5,-1268.84 h60
  text "PLOT NAME =" at 6246,-1268.84 h60
M9 Title Sheet:
  drawing of 57 lines, arcs and shapes, not listed
  text "1" at 739.84,7832.5 h70
  text "2" at 3235.5,7832.5 h70
  text "3" at 5724.84,7832.5 h70
  text "4" at 8231.51,7832.5 h70
  text "5" at 10730.5,7832.5 h70
  text "6" at 13235.5,7832.5 h70
  text "A" at -416.5,6689.5 h70
  text "A" at 14383.5,6689.5 h70
  text "B" at -416.5,4309.5 h70
  text "B" at 14383.5,4309.5 h70
  text "C" at -416.5,1934.5 h70
  text "C" at 14383.5,1934.5 h70
  text "PROJECT TITLE:" at 11343.5,73.5 h45
  text ".PRJ_Title" at 11393.5,-59.83 h70
  text "DESIGNED FOR:" at 11343.5,-227.5 h45
  text ".PRJ_Customer" at 11393.5,-367.5 h70
  text "D" at -416.5,-435.5 h70
  text "D" at 14383.5,-435.5 h70
  text "FILE NAME:" at 11343.5,-527.5 h45
  text ".PCB_File_Name_No_Path" at 11393.5,-647.5 h70
  text "Texas Instruments (TI) and/or its licensors do not warrant the accuracy or completeness of this specification" at 6374,-809.34 h45
  text "ENGINEER:" at 11343.5,-817.5 h45
  text "LAYOUT BY:" at 12848.5,-817.5 h45
  text "or any information contained therein. TI and/or its licensors do not warrant that this design will meet" at 6329.01,-922 h45
  text ".PRJ_Engineer" at 11393.5,-972.49 h70
  text ".PCB_Layout" at 12899,-972.49 h70
  text "the specifications, will be suitable for your application or fit for any particular purpose, or will operate in" at 6329.01,-1034.67 h45
  text "ALTIUM DESIGNER VERSION:" at 12848.5,-1127.5 h45
  text "an implementation. TI and/or its licensors do not warrant that the design is production worthy. You should" at 6329.01,-1147.33 h45
  text "completely validate and test your design implementation to confirm the system functionality for your application." at 6374,-1260 h45
  text ".print_Scale" at 11393.5,-1260.83 h70
  text ".Application_BuildNumber" at 12899,-1260.83 h70
  text "1" at 739.84,-1467.5 h70
  text "2" at 3235.5,-1467.5 h70
  text "3" at 5724.84,-1467.5 h70
  text "4" at 8231.51,-1467.5 h70
  text "5" at 10730.5,-1467.5 h70
  text "6" at 13235.5,-1467.5 h70
M10 Fab Notes:
  drawing of 185 lines, arcs and shapes, not listed
  text "DESIGN INFORMATION" at 12381.02,5706 h60
  text "MIN. TRACK WIDTH:" at 11736.46,5526 h60
  text "4" at 12832.7,5526 h60
  text "MIL" at 12987.46,5526 h60
  text "MIN. CLEARANCE:" at 11736.46,5394 h60
  text "0.2" at 12772.7,5394 h60
  text "mm" at 12987.46,5394 h60
  text "MIN. VIA PAD SIZE:" at 11736.46,5262 h60
  text "6" at 12802.71,5262 h60
  text "MIL" at 12987.46,5262 h60
  text "0.05mm (2MIL)" at 12431.46,5120.29 h60
  text "MINIMUM ANNULAR RING" at 11407.23,5116 h60
  text "EXTERNAL" at 13139.46,5116 h60
  text "PER" at 11607.23,4998 h60
  text "IPC-D-275 CLASS 2 LEVEL C" at 11827.23,4998 h60
  text "MIL, HOLES" at 13315.46,4885.71 h60
  text "+/-" at 12923,4885 h60
  text "+/-" at 13777,4885 h60
  text "REGISTRATION TOLERANCES:" at 11407.23,4880 h60
  text "METAL" at 12607,4880 h60
  text "5" at 13183.2,4880 h60
  text "3" at 14016.2,4880 h60
  text "MIL" at 14132.46,4880 h60
  text "MATERIAL:" at 11332.46,4670.54 h60
  text "FR-4 High Tg" at 12318.9,4530.21 h60
  text "FR-408" at 11753.46,4521.64 h60
  text "X" at 12165.46,4521.64 h60
  text "OTHER" at 13241.46,4521.64 h60
  text "62 MIL (1.6mm) +/-10%" at 12073.56,4358.92 h60
  text "THICKNESS:" at 11407.23,4354.64 h60
  text "X" at 11945.4,4354.64 h60
  text "OTHER" at 13358.46,4354.64 h60
  text "TOLERANCE:" at 11407.23,4196.64 h60
  text "X" at 12246.53,4196.64 h60
  text "ANSI IPC-6012 TYPE 3 CLASS 2" at 12433.48,4196.64 h60
  text "OTHER +/-" at 12433.46,4040.64 h60
  text "BOW & TWIST:" at 11407.23,3883.64 h60
  text "X" at 12246.53,3883.64 h60
  text "ANSI IPC-6012 TYPE 3 CLASS 2" at 12433.48,3883.64 h60
  text "OTHER +/-" at 12433.46,3725.13 h60
  text "DRILLING:" at 11332.46,3586.64 h60
  text "REFERENCE:" at 11407.23,3469.64 h60
  text "X" at 12055.46,3469.64 h60
  text "AS SHOWN" at 12242.46,3469.64 h60
  text "X" at 12956.46,3469.64 h60
  text "NC_DRILL FILES" at 13093.46,3469.64 h60
  text "PTH MIN COPPER THICKNESS:" at 11407.23,3311.64 h60
  text "X" at 12757.46,3311.64 h60
  text "1MIL" at 12894.46,3311.64 h60
  text "OTHER" at 13391.46,3311.64 h60
  text "BOARD FINISH:" at 11332.46,3152.64 h60
  text "SILKSCREEN:" at 11487.68,3034.64 h60
  text "X" at 12436.46,3034.64 h60
  text "TOP" at 12562.46,3034.64 h60
  text "X" at 12946.46,3034.64 h60
  text "BOTTOM" at 13073.46,3034.64 h60
  text "SILKSCREEN COLOR:" at 11487.68,2867.64 h60
  text "X" at 12435.42,2867.64 h60
  text "WHITE" at 12562.46,2867.64 h60
  text "OTHER" at 13073.46,2867.64 h60
  text "SOLDER RESIST COLOR:" at 11487.68,2697.64 h60
  text "X" at 12055.42,2538.44 h60
  text "GREEN" at 12182.46,2538.44 h60
  text "BLUE" at 12773.46,2538.44 h60
  text "OTHER" at 13311.46,2538.44 h60
  text "IMMERSION GOLD (ENIG)" at 12393.46,2349.92 h60
  text "ENEPIG" at 13731,2346.64 h60
  text "SURFACE FINISH:" at 11332.46,2345.64 h60
  text "X" at 12206.51,2345.64 h60
  text "IMM. TIN/SILVER OR EQUIV" at 11662,2188.64 h60
  text "OTHER" at 13093.46,2188.64 h60
  text "ARRAY/PANEL:" at 11332.46,2009.64 h60
  text "CUT AND TRIM PER MECH LAYER 1" at 12393.46,2005.35 h60
  text "4.5mil traces on layer 2 and layer 4" at 4572,1887 h100
  text "N.C. ROUTE" at 12393.46,1853.64 h60
  text "X" at 13072.46,1853.64 h60
  text "V. SCORE" at 13259.46,1853.64 h60
  text "Need to be 50 ohm single ended impedance" at 4602,1729 h100
  text "CERTIFICATION:" at 11332.46,1716.64 h60
  text "MATERIALS AND WORKMANSHIP FOR ALL PCBS" at 12057.46,1716.64 h60
  text "TO MEET OR EXCEED THE REQUIREMENTS OF:" at 12057.46,1618.64 h60
  text "X" at 11683.96,1482.13 h60
  text "ANSI IPC-A-600F CLASS ->" at 11822.96,1482.13 h60
  text "X" at 13462.02,1482.13 h60
  text "2" at 13580.96,1482.14 h60
  text "1" at 13265.96,1480.64 h60
  text "3" at 13934.96,1480.64 h60
  text "Top and bottom layer traces that are 11 mils wide" at 4557,1402 h100
  text "X" at 11686.02,1322.64 h60
  text "UL 94V-0" at 11822.96,1322.64 h60
  text "X" at 12498.02,1322.64 h60
  text "RoHS" at 12634.96,1322.64 h60
  text "OTHER" at 13279.36,1322.64 h60
  text "PER ORDER" at 13676.42,1322.64 h60
  text "and 16 mils apart are 100 ohm differential" at 4582,1242 h100
  text "ADDITIONAL REQUIREMENTS:" at 11332.46,1181.64 h60
  text "MICROSECTION:" at 11407.23,1066.64 h60
  text "YES" at 12312.96,1066.64 h60
  text "REQUIRED" at 13174.46,910.49 h60
  text "BARE BOARD ELEC. TEST:" at 11407.23,907.64 h60
  text "NONE" at 12712.96,907.64 h60
  text "X" at 13047.46,907.64 h60
  text "PER ORDER" at 13766.46,907.64 h60
  text "Layer 1 and Layer 4 traces that are 4.5 mils wide" at 4607,776 h100
  text "MANUFACTURER'S UL:" at 11407.23,750.64 h60
  text "RAIL" at 12572.96,746.35 h60
  text "METAL" at 13064.77,746.35 h60
  text "X" at 13440,746 h60
  text "SILK" at 13576.46,746.35 h60
  text "and 16 mils apart are 100 ohm differential" at 4582,635 h100
M11 Gerber Information:
  lines w10: -292,-1134.17 6308,-1134.17 ; -292,-930.83 6310,-930.83 ; -292,-727.5 -292,-1337.5 3713,-1337.5 6310,-1337.5 6310,-727.5 -291.5,-727.5 -291.5,-1337.5 1284,-1337.5 ; 2173,-1337.5 2173,-727.5 ; 3440,-930.83 3440,-727.5 ; 4280,-930.83 4280,-727.5 ; 4902,-1344 4902,-1141.17
  text "ALL ARTWORK VIEWED FROM TOP SIDE" at -228.5,-859.67 h60
  text "BOARD #:" at 2248,-859.67 h60
  text ".PRJ_Number" at 2793.5,-859.67 h60
  text "REV:" at 3638,-859.67 h60
  text ".PCB_Rev" at 3929.5,-859.67 h60
  text "SVN REV:" at 4476,-859.67 h60
  text ".VersionControl_RevNumber" at 4982,-859.67 h60
  text "LAYER NAME =" at -228.5,-1062.49 h60
  text "TID #:" at 2248,-1063 h60
  text ".TID" at 2793.5,-1063 h60
  text "PLOT NAME =" at -228.5,-1268.34 h60
  text ".plot_File_Name" at 577,-1268.34 h60
  text "GENERATED    :" at 2250,-1268.34 h60
  text ".Print_Date" at 3119.5,-1268.34 h60
  text ".Print_Time" at 3848.5,-1268.34 h60
  text "TEXAS INSTRUMENTS" at 5113,-1268.34 h60
M12 Stackup:
  drawing of 399 lines, arcs and shapes, not listed
  text "Layer" at 9811,7664 h60
  text "Name" at 10220.91,7664 h60
  text "Material" at 11160.65,7664 h60
  text "Thickness" at 12020.42,7664 h60
  text "Constant" at 12670.26,7664 h60
  text "Board Layer Stack" at 13240.12,7664 h60
  text "1" at 9811,7544 h60
  text "Top Overlay" at 10220.91,7544 h60
  text "2" at 9811,7424 h60
  text "Top Solder" at 10220.91,7424 h60
  text "Solder Resist" at 11160.65,7424 h60
  text "0.70mil" at 12020.42,7424 h60
  text "3.5" at 12670.26,7424 h60
  text "3" at 9811,7304 h60
  text "Top Layer" at 10220.91,7304 h60
  text "Copper" at 11160.65,7304 h60
  text "1.58mil" at 12020.42,7304 h60
  text "4" at 9811,7184 h60
  text "Dielectric1" at 10220.91,7184 h60
  text "FR-4" at 11160.65,7184 h60
  text "5.00mil" at 12020.42,7184 h60
  text "4.8" at 12670.26,7184 h60
  text "5" at 9811,7064 h60
  text "Signal Layer 1" at 10220.91,7064 h60
  text "Copper" at 11160.65,7064 h60
  text "1.30mil" at 12020.42,7064 h60
  text "6" at 9811,6944 h60
  text "Dielectric 3" at 10220.91,6944 h60
  text "6.00mil" at 12020.42,6944 h60
  text "4.2" at 12670.26,6944 h60
  text "7" at 9811,6824 h60
  text "Signal Layer 2" at 10220.91,6824 h60
  text "Copper" at 11160.65,6824 h60
  text "1.30mil" at 12020.42,6824 h60
  text "8" at 9811,6704 h60
  text "Dielectric 2" at 10220.91,6704 h60
  text "30.00mil" at 12020.42,6704 h60
  text "4.2" at 12670.26,6704 h60
  text "9" at 9811,6584 h60
  text "Signal Layer 3" at 10220.91,6584 h60
  text "Copper" at 11160.65,6584 h60
  text "1.30mil" at 12020.42,6584 h60
  text "10" at 9811,6464 h60
  text "Dielectric 5" at 10220.91,6464 h60
  text "6.00mil" at 12020.42,6464 h60
  text "4.2" at 12670.26,6464 h60
  text "11" at 9811,6344 h60
  text "Signal Layer 4" at 10220.91,6344 h60
  text "Copper" at 11160.65,6344 h60
  text "1.30mil" at 12020.42,6344 h60
  text "12" at 9811,6224 h60
  text "Dielectric 4" at 10220.91,6224 h60
  text "5.00mil" at 12020.42,6224 h60
  text "4.2" at 12670.26,6224 h60
  text "13" at 9811,6104 h60
  text "Bottom Layer" at 10220.91,6104 h60
  text "Copper" at 11160.65,6104 h60
  text "1.58mil" at 12020.42,6104 h60
  text "14" at 9811,5984 h60
  text "Bottom Solder" at 10220.91,5984 h60
  text "Solder Resist" at 11160.65,5984 h60
  text "0.70mil" at 12020.42,5984 h60
  text "3.5" at 12670.26,5984 h60
  text "15" at 9811,5864 h60
  text "Bottom Overlay" at 10220.91,5864 h60
Drill Drawing:
  drawing of 154 lines, arcs and shapes, not listed
  text "Symbol" at 5071,5476 h72
  text "Hit Count" at 5576.88,5476 h72
  text "Finished Hole Size" at 6274.69,5476 h72
  text "Plated" at 7620.29,5476 h72
  text "Hole Type" at 8126.17,5476 h72
  text "Physical Length" at 8859.97,5476 h72
  text "Rout Path Length" at 10001.64,5476 h72
  text "1" at 5576.88,5326 h60
  text "12.00mil (0.305mm)" at 6274.69,5326 h60
  text "PTH" at 7620.29,5326 h60
  text "Round" at 8126.17,5326 h60
  text "1" at 5576.88,5176 h60
  text "33.46mil (0.850mm)" at 6274.69,5176 h60
  text "PTH" at 7620.29,5176 h60
  text "Round" at 8126.17,5176 h60
  text "E" at 5061.62,5038.5 h50
  text "2" at 5576.88,5026 h60
  text "23.62mil (0.600mm)" at 6274.69,5026 h60
  text "PTH" at 7620.29,5026 h60
  text "Slot" at 8126.17,5026 h60
  text "51.18mil (1.300mm)" at 8859.97,5026 h60
  text "27.56mil (0.700mm)" at 10001.64,5026 h60
  text "F" at 5061.62,4888.5 h50
  text "2" at 5576.88,4876 h60
  text "27.56mil (0.700mm)" at 6274.69,4876 h60
  text "PTH" at 7620.29,4876 h60
  text "Slot" at 8126.17,4876 h60
  text "33.46mil (0.850mm)" at 8859.97,4876 h60
  text "5.91mil (0.150mm)" at 10001.64,4876 h60
  text "2" at 5576.88,4726 h60
  text "61.02mil (1.550mm)" at 6274.69,4726 h60
  text "NPTH" at 7620.29,4726 h60
  text "Round" at 8126.17,4726 h60
  text "2" at 5576.88,4576 h60
  text "61.81mil (1.570mm)" at 6274.69,4576 h60
  text "PTH" at 7620.29,4576 h60
  text "Round" at 8126.17,4576 h60
  text "D" at 5061.62,4438.5 h50
  text "2" at 5576.88,4426 h60
  text "128.00mil (3.251mm)" at 6274.69,4426 h60
  text "PTH" at 7620.29,4426 h60
  text "Round" at 8126.17,4426 h60
  text "3" at 5576.88,4276 h60
  text "40.16mil (1.020mm)" at 6274.69,4276 h60
  text "PTH" at 7620.29,4276 h60
  text "Round" at 8126.17,4276 h60
  text "C" at 5061.62,4138.5 h50
  text "4" at 5576.88,4126 h60
  text "126.00mil (3.200mm)" at 6274.69,4126 h60
  text "PTH" at 7620.29,4126 h60
  text "Round" at 8126.17,4126 h60
  text "5" at 5576.88,3976 h60
  text "7.87mil (0.200mm)" at 6274.69,3976 h60
  text "PTH" at 7620.29,3976 h60
  text "Round" at 8126.17,3976 h60
  text "A" at 5061.62,3838.5 h50
  text "7" at 5576.88,3826 h60
  text "98.43mil (2.500mm)" at 6274.69,3826 h60
  text "PTH" at 7620.29,3826 h60
  text "Round" at 8126.17,3826 h60
  text "8" at 5576.88,3676 h60
  text "35.04mil (0.890mm)" at 6274.69,3676 h60
  text "PTH" at 7620.29,3676 h60
  text "Round" at 8126.17,3676 h60
  text "9" at 5576.88,3526 h60
  text "37.40mil (0.950mm)" at 6274.69,3526 h60
  text "PTH" at 7620.29,3526 h60
  text "Round" at 8126.17,3526 h60
  text "10" at 5576.88,3376 h60
  text "10.00mil (0.254mm)" at 6274.69,3376 h60
  text "PTH" at 7620.29,3376 h60
  text "Round" at 8126.17,3376 h60
  text "10" at 5576.88,3226 h60
  text "41.34mil (1.050mm)" at 6274.69,3226 h60
  text "PTH" at 7620.29,3226 h60
  text "Round" at 8126.17,3226 h60
  text "58" at 5576.88,3076 h60
  text "40.00mil (1.016mm)" at 6274.69,3076 h60
  text "PTH" at 7620.29,3076 h60
  text "Round" at 8126.17,3076 h60
  text "74" at 5576.88,2926 h60
  text "6.00mil (0.152mm)" at 6274.69,2926 h60
  text "PTH" at 7620.29,2926 h60
  text "Round" at 8126.17,2926 h60
  text "107" at 5576.88,2776 h60
  text "11.00mil (0.279mm)" at 6274.69,2776 h60
  text "PTH" at 7620.29,2776 h60
  text "Round" at 8126.17,2776 h60
  text "307 Total" at 5576.88,2626 h60

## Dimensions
0,-604 to 1000,-604 on M2 Board Dimensions
0,-204 to 0,4037 on M2 Board Dimensions
0,-204 to 3713,0 on M2 Board Dimensions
